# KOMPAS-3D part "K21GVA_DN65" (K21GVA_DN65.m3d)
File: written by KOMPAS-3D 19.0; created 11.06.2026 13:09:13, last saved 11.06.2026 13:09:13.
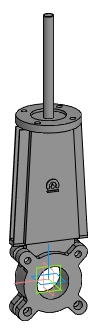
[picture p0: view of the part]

Document properties: Автор: Энергия; Полное имя файла: Z:\3.Личные\kachalov\001_3d для проектировщиков\2.5 Тип_K21GVA. Задвижка\_stp\_stp_K21GVA_DN50-DN1000_с фланцем\K21GVA_DN65.m3d

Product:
- Part/product: K21GVA_DN65

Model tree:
1. Операция без истории:1  (labels: K21GVA_DN65)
